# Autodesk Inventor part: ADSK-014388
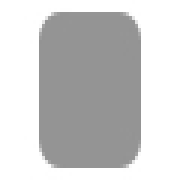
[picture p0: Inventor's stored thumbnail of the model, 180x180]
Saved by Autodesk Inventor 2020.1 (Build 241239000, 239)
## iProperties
Created: 2019-01
Part Number: ADSK-014388
Material: Stahl, weich
Document SubType Name: Modeling
Designer: lutzd
Language: de-DE
Size Designation: 5 x 60 x 40
Categories: <MemberInstance><Categories><Category DisplayName="Sonstige Bauteile" InternalName="5aa15e00-363f-49f2-933f-16f664388e3f" Mnemonic="OTHER"><Category DisplayName
Mass: 93.3577 g
Surface Area: 57.1416 cm^2
Volume: 11.8927 cm^3
Density: 7.85 g/cm^3
Appearance: Semi-Polished(8)
IsCustomPart: 1
Title: end cap
Author: lutzd
Revision Number: -
DocNumber: ADSK-014388
Folder: 01 - Themengebiete\Simplification\01 - Packaging machine\Parts\
VDS_Category: 3D Komponenten
VDS_NumSchm: Autodesk
Mass: 0,093 kg
VLT_Material: Stahl, weich
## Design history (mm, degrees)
sketch "Sketch1"
  geometry: L1 (0, 20.175)-(0, -21.446); L2 (-20.203, 0)-(20.169, 0); L3 (-20, 30)-(20, 30); L4 (20, 30)-(20, -30); L5 (20, -30)-(-20, -30); L6 (-20, -30)-(-20, 30); 1 further point
  constraints: 12 end point, 2 horizontal, 2 parallel, 2 point on line, 1 perpendicular, 1 vertical
  dimensions: "d0" = 60 distance between parallel lines of L5 L3 (= height); "d1" = 30 distance between parallel lines of L2 L3 (= 0.5 x height); "d2" = 40 distance between parallel lines of L6 L4 (= width); "d3" = 20 distance between parallel lines of L6 L1 (= 0.5 x width)
extrude "Extrusion1" new body sketch "Sketch1" distance "d4" = 5 (= thickness); taper "d5" = 0 deg
fillet "Fillet1" dims "d6" = 5 (= fillet), "d7" = 0, "fillet" = 5 [user parameter; used in 1 equation term]
chamfer "Chamfer1" distance "d8" = 0 (computed from chamfer); stored, may be unused: second distance "d9" = 2, angle "d10" = 45 deg; dims "d11" = 0, "chamfer" = 0 [user parameter; used in 1 equation term]
body "Solid1"
other parameters: "thickness" = 5 [user parameter; used in 1 equation term], "width" = 40 [user parameter; used in 2 equation terms], "height" = 60 [user parameter; used in 2 equation terms]
